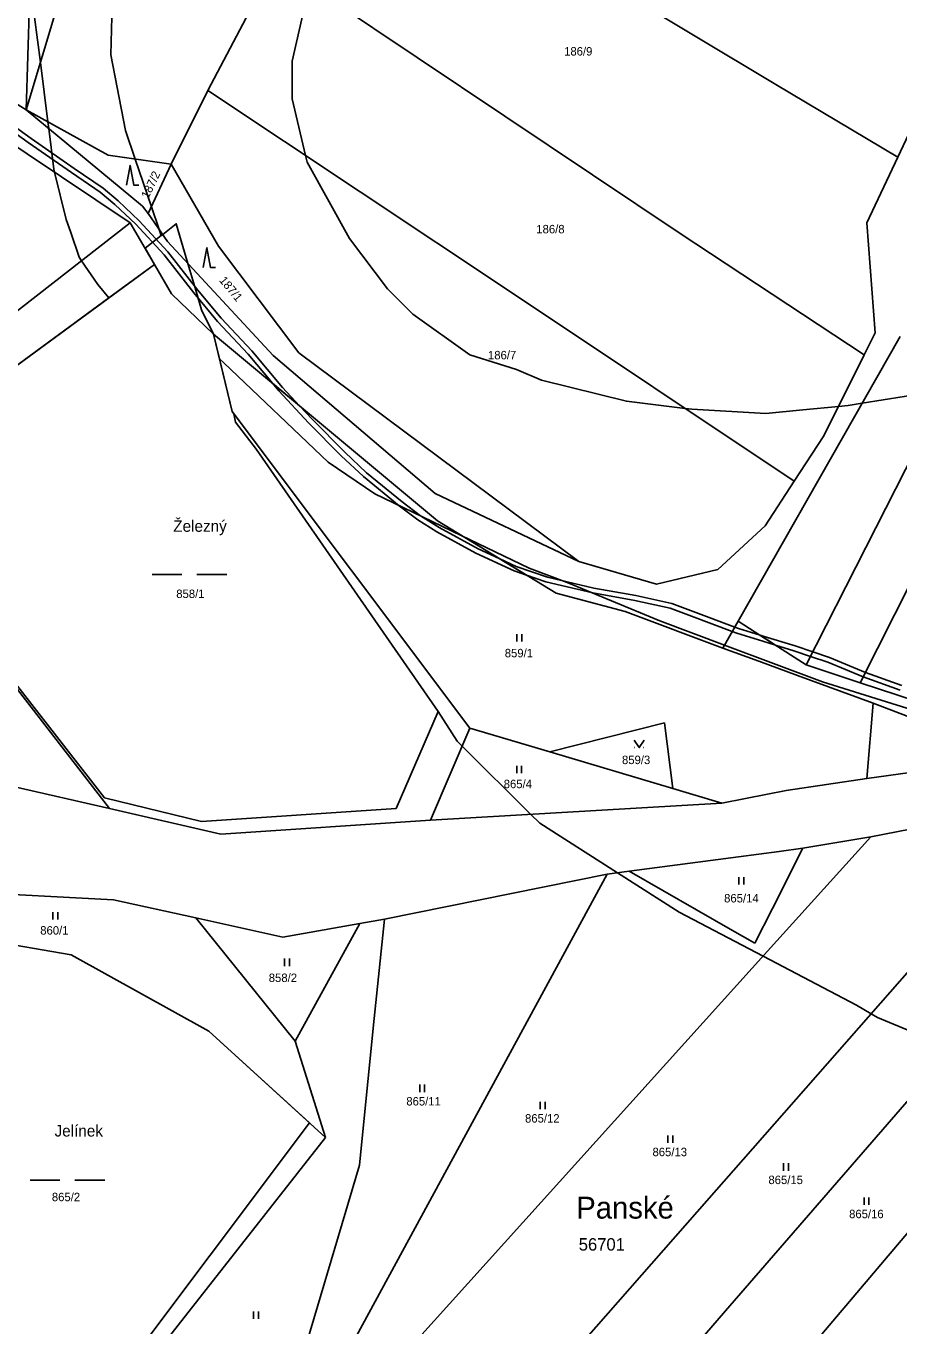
# Model space of a CAD drawing. Extents: x -749173 to -746119, y -1132678 to -1130338.
# Drawn here: x -747283.8 to -747108.1, y -1131870.4 to -1131608.6 of the extents above; entities that cross this region are included whole.
import ezdxf

# ---------------------------------------------------------------- set-up
doc = ezdxf.new("R2010")
doc.units = 0
for name, color, linetype in [('Vrstva 1', 7, 'Continuous'), ('Vrstva 15', 7, 'Continuous'), ('Vrstva 18', 7, 'Continuous'), ('Vrstva 25', 7, 'Continuous'), ('Vrstva 30', 7, 'Continuous'), ('Vrstva 52', 7, 'Continuous'), ('Vrstva 53', 7, 'Continuous'), ('Vrstva 6', 7, 'Continuous')]:
    doc.layers.add(name, color=color, linetype=linetype)

msp = doc.modelspace()

# ---------------------------------------------------------------- linework, layer by layer
at = {"layer": 'Vrstva 1'}
for points in [[(-747283.76, -1131625.43), (-747282.45, -1131581.86)], [(-747273.69, -1131591.9), (-747283.76, -1131625.43)], [(-747108.32, -1131634.98), (-747091.75, -1131599.73)], [(-747305.55, -1131611.85), (-747283.76, -1131625.43)], [(-747283.76, -1131625.43), (-747267.27, -1131634.55)], [(-747283.76, -1131625.43), (-747260.33, -1131644.82)], [(-747290.52, -1131629.64), (-747262.86, -1131648.18)], [(-747267.27, -1131634.55), (-747254.6, -1131636.41)], [(-747254.6, -1131636.41), (-747245.07, -1131652.89)], [(-747114.54, -1131648.21), (-747108.32, -1131634.98)], [(-747260.33, -1131644.82), (-747259.18, -1131646.33)], [(-747259.18, -1131646.33), (-747255.29, -1131651.97)], [(-747322.41, -1131694.68), (-747262.86, -1131648.18)], [(-747262.86, -1131648.18), (-747257.91, -1131656.57)], [(-747112.86, -1131670.34), (-747114.54, -1131648.21)], [(-747255.29, -1131651.97), (-747234.06, -1131674.93)], [(-747245.07, -1131652.89), (-747228.87, -1131674.36)], [(-747317.79, -1131700.5), (-747257.91, -1131656.57)], [(-747257.91, -1131656.57), (-747254.48, -1131662.48)], [(-747254.48, -1131662.48), (-747246.06, -1131670.63)], [(-747200.93, -1131708.24), (-747246.06, -1131670.63)], [(-747246.06, -1131670.63), (-747242.32, -1131686.21)], [(-747107.8, -1131671.12), (-747140.43, -1131728.4)], [(-747115.08, -1131674.81), (-747112.86, -1131670.34)], [(-747234.06, -1131674.93), (-747201.42, -1131702.74)], [(-747228.87, -1131674.36), (-747172.52, -1131716.41)], [(-747123.18, -1131691.12), (-747115.08, -1131674.81)], [(-747242.32, -1131686.21), (-747194.42, -1131749.94)], [(-747129.15, -1131700.25), (-747123.18, -1131691.12)], [(-747267.01, -1131766.16), (-747317.79, -1131700.5)], [(-747135, -1131709.19), (-747129.15, -1131700.25)], [(-747201.42, -1131702.74), (-747172.52, -1131716.41)], [(-747177.09, -1131722.8), (-747200.93, -1131708.24)], [(-747144.51, -1131718.02), (-747135, -1131709.19)], [(-747172.52, -1131716.41), (-747156.9, -1131720.96)], [(-747156.9, -1131720.96), (-747144.51, -1131718.02)], [(-747163.2, -1131726.49), (-747177.09, -1131722.8)], [(-747143.51, -1131733.86), (-747163.2, -1131726.49)], [(-747140.43, -1131728.4), (-747143.51, -1131733.86)], [(-747135.85, -1131731.36), (-747140.43, -1131728.4)], [(-747128.24, -1131736.28), (-747135.85, -1131731.36)], [(-747136.3, -1131736.51), (-747143.51, -1131733.86)], [(-747128.51, -1131739.37), (-747136.3, -1131736.51)], [(-747126.73, -1131737.25), (-747128.24, -1131736.28)], [(-747115.85, -1131740.82), (-747126.73, -1131737.25)], [(-747113.28, -1131744.96), (-747128.51, -1131739.37)], [(-747104.57, -1131744.53), (-747115.85, -1131740.82)], [(-747113.28, -1131744.96), (-747114.55, -1131760.12)], [(-747084.49, -1131755.95), (-747113.28, -1131744.96)], [(-747178.35, -1131754.73), (-747155.26, -1131748.88)], [(-747153.61, -1131762.1), (-747155.26, -1131748.88)], [(-747194.42, -1131749.94), (-747202.38, -1131768.48)], [(-747194.42, -1131749.94), (-747178.35, -1131754.73)], [(-747178.35, -1131754.73), (-747153.61, -1131762.1)], [(-747114.55, -1131760.12), (-747084.49, -1131755.95)], [(-747130.74, -1131762.5), (-747114.55, -1131760.12)], [(-747267.01, -1131766.16), (-747286.37, -1131761.74)], [(-747153.61, -1131762.1), (-747143.72, -1131765.05)], [(-747138.98, -1131764.12), (-747130.74, -1131762.5)], [(-747143.72, -1131765.05), (-747202.38, -1131768.48)], [(-747143.72, -1131765.05), (-747138.98, -1131764.12)], [(-747075.87, -1131764.45), (-747113.75, -1131771.83)], [(-747244.55, -1131771.35), (-747267.01, -1131766.16)], [(-747202.38, -1131768.48), (-747244.55, -1131771.35)], [(-747113.75, -1131771.83), (-747127.4, -1131774.15)], [(-747140.35, -1131775.86), (-747162.4, -1131778.78)], [(-747132.18, -1131774.78), (-747140.35, -1131775.86)], [(-747127.4, -1131774.15), (-747132.18, -1131774.78)], [(-747166.79, -1131779.35), (-747211.65, -1131788.43)], [(-747162.4, -1131778.78), (-747166.79, -1131779.35)], [(-747296.48, -1131782.93), (-747266.19, -1131784.57)], [(-747266.19, -1131784.57), (-747249.62, -1131788.14)], [(-747249.62, -1131788.14), (-747232.12, -1131792.08)], [(-747229.61, -1131813), (-747249.62, -1131788.14)], [(-747211.65, -1131788.43), (-747216.62, -1131789.31)], [(-747213.89, -1131810.39), (-747211.65, -1131788.43)], [(-747274.72, -1131795.65), (-747308.97, -1131789.7)], [(-747232.12, -1131792.08), (-747216.62, -1131789.31)], [(-747216.62, -1131789.31), (-747229.61, -1131813)], [(-747246.96, -1131810.99), (-747274.72, -1131795.65)], [(-747223.51, -1131832.44), (-747246.96, -1131810.99)], [(-747216.68, -1131837.99), (-747213.89, -1131810.39)], [(-747229.61, -1131813), (-747223.51, -1131832.44)], [(-747265.2, -1131885.54), (-747223.51, -1131832.44)], [(-747230.08, -1131883.19), (-747216.68, -1131837.99)]]:
    msp.add_lwpolyline(points, dxfattribs=at)
at = {"layer": 'Vrstva 25'}
for p, q in [((-747258.4, -1131719.04), (-747252.4, -1131719.04)), ((-747249.4, -1131719.04), (-747243.4, -1131719.04)), ((-747185, -1131731.02), (-747185, -1131732.52)), ((-747184, -1131732.52), (-747184, -1131731.02)), ((-747161.31, -1131753.88), (-747161.21, -1131753.88)), ((-747159.51, -1131753.88), (-747159.41, -1131753.88)), ((-747185.02, -1131757.53), (-747185.02, -1131759.03)), ((-747184.02, -1131759.03), (-747184.02, -1131757.53)), ((-747140.27, -1131779.99), (-747140.27, -1131781.49)), ((-747139.27, -1131781.49), (-747139.27, -1131779.99)), ((-747278.37, -1131787.02), (-747278.37, -1131788.52)), ((-747277.37, -1131788.52), (-747277.37, -1131787.02)), ((-747231.74, -1131796.39), (-747231.74, -1131797.89)), ((-747230.74, -1131797.89), (-747230.74, -1131796.39)), ((-747204.55, -1131821.77), (-747204.55, -1131823.27)), ((-747203.55, -1131823.27), (-747203.55, -1131821.77)), ((-747180.28, -1131825.21), (-747180.28, -1131826.71)), ((-747179.28, -1131826.71), (-747179.28, -1131825.21)), ((-747154.61, -1131831.98), (-747154.61, -1131833.48)), ((-747153.61, -1131833.48), (-747153.61, -1131831.98)), ((-747131.31, -1131837.6), (-747131.31, -1131839.1)), ((-747130.31, -1131839.1), (-747130.31, -1131837.6)), ((-747282.96, -1131841), (-747276.96, -1131841)), ((-747273.96, -1131841), (-747267.96, -1131841)), ((-747115.1, -1131844.47), (-747115.1, -1131845.97)), ((-747114.1, -1131845.97), (-747114.1, -1131844.47)), ((-747238, -1131867.43), (-747238, -1131868.93)), ((-747237, -1131868.93), (-747237, -1131867.43))]:
    msp.add_line(p, q, dxfattribs=at)
for points in [[(-747263.59, -1131640.62), (-747262.84, -1131636.62), (-747262.09, -1131640.62), (-747261.09, -1131640.62)], [(-747248.13, -1131657.21), (-747247.38, -1131653.21), (-747246.63, -1131657.21), (-747245.63, -1131657.21)], [(-747161.36, -1131752.38), (-747160.36, -1131753.88), (-747159.36, -1131752.38)]]:
    msp.add_lwpolyline(points, dxfattribs=at)
at = {"layer": 'Vrstva 30'}
for points in [[(-747283.36, -1131632.04), (-747292.6, -1131625.39)], [(-747292.02, -1131624.57), (-747282.78, -1131631.22)], [(-747282.78, -1131631.22), (-747274.1, -1131637.24)], [(-747274.66, -1131638.06), (-747283.36, -1131632.04)], [(-747268.88, -1131641.99), (-747274.66, -1131638.06)], [(-747274.1, -1131637.24), (-747268.28, -1131641.19)], [(-747265.94, -1131644.47), (-747268.88, -1131641.99)], [(-747268.28, -1131641.19), (-747265.26, -1131643.73)], [(-747261.71, -1131648.47), (-747265.94, -1131644.47)], [(-747265.26, -1131643.73), (-747261, -1131647.77)], [(-747255.99, -1131654.66), (-747261.71, -1131648.47)], [(-747261, -1131647.77), (-747255.23, -1131654.02)], [(-747250.04, -1131662.3), (-747255.99, -1131654.66)], [(-747255.23, -1131654.02), (-747249.26, -1131661.66)], [(-747245.22, -1131668.05), (-747250.04, -1131662.3)], [(-747249.26, -1131661.66), (-747244.48, -1131667.39)], [(-747239.07, -1131674.66), (-747245.22, -1131668.05)], [(-747244.48, -1131667.39), (-747238.33, -1131674)], [(-747234.19, -1131680.52), (-747239.07, -1131674.66)], [(-747238.33, -1131674), (-747232.17, -1131681.39)], [(-747232.91, -1131682.05), (-747234.19, -1131680.52)], [(-747234.19, -1131680.52), (-747228.73, -1131685.07)], [(-747228.73, -1131685.07), (-747234.19, -1131680.52)], [(-747232.17, -1131681.39), (-747228.73, -1131685.07)], [(-747226.94, -1131688.46), (-747232.91, -1131682.05)], [(-747228.73, -1131685.07), (-747226.22, -1131687.76)], [(-747220.32, -1131695.09), (-747226.94, -1131688.46)], [(-747226.22, -1131687.76), (-747219.62, -1131694.37)], [(-747219.62, -1131694.37), (-747215.23, -1131698.52)], [(-747215.89, -1131699.28), (-747220.32, -1131695.09)], [(-747208.69, -1131705.2), (-747215.89, -1131699.28)], [(-747215.23, -1131698.52), (-747208.07, -1131704.42)], [(-747204.94, -1131708.02), (-747208.69, -1131705.2)], [(-747208.07, -1131704.42), (-747204.37, -1131707.2)], [(-747204.37, -1131707.2), (-747200.6, -1131709.57)], [(-747201.12, -1131710.43), (-747204.94, -1131708.02)], [(-747193.24, -1131714.74), (-747201.12, -1131710.43)], [(-747200.6, -1131709.57), (-747192.78, -1131713.84)], [(-747185.52, -1131718.31), (-747193.24, -1131714.74)], [(-747192.78, -1131713.84), (-747188.52, -1131715.82)], [(-747188.52, -1131715.82), (-747185.14, -1131717.39)], [(-747188.52, -1131715.82), (-747183.02, -1131719.18)], [(-747183.02, -1131719.18), (-747188.52, -1131715.82)], [(-747185.14, -1131717.39), (-747178.84, -1131719.57)], [(-747183.02, -1131719.18), (-747185.52, -1131718.31)], [(-747179.12, -1131720.53), (-747183.02, -1131719.18)], [(-747169.7, -1131722.73), (-747179.12, -1131720.53)], [(-747178.84, -1131719.57), (-747169.5, -1131721.75)], [(-747161.21, -1131724.25), (-747169.7, -1131722.73)], [(-747169.5, -1131721.75), (-747161.02, -1131723.27)], [(-747161.02, -1131723.27), (-747153.81, -1131724.86)], [(-747154.09, -1131725.82), (-747161.21, -1131724.25)], [(-747149.86, -1131727.41), (-747154.09, -1131725.82)], [(-747153.81, -1131724.86), (-747149.5, -1131726.47)], [(-747141.62, -1131730.51), (-747149.86, -1131727.41)], [(-747149.5, -1131726.47), (-747141.12, -1131729.63)], [(-747140.69, -1131730.86), (-747141.62, -1131730.51)], [(-747141.12, -1131729.63), (-747140.35, -1131729.92)], [(-747135.5, -1131732.46), (-747140.69, -1131730.86)], [(-747140.35, -1131729.92), (-747136.02, -1131731.25)], [(-747136.02, -1131731.25), (-747135.2, -1131731.5)], [(-747132.95, -1131733.24), (-747136.02, -1131731.25)], [(-747136.02, -1131731.25), (-747132.95, -1131733.24)], [(-747132.95, -1131733.24), (-747135.5, -1131732.46)], [(-747135.2, -1131731.5), (-747128.94, -1131733.41)], [(-747129.24, -1131734.37), (-747132.95, -1131733.24)], [(-747128.94, -1131733.41), (-747125.4, -1131734.62)], [(-747125.85, -1131735.53), (-747129.24, -1131734.37)], [(-747125.85, -1131735.53), (-747125.4, -1131734.62)], [(-747125.4, -1131734.62), (-747125.85, -1131735.53)], [(-747122.39, -1131736.71), (-747125.85, -1131735.53)], [(-747125.4, -1131734.62), (-747122.04, -1131735.77)], [(-747122.04, -1131735.77), (-747114.8, -1131738.74)], [(-747115.26, -1131739.64), (-747122.39, -1131736.71)], [(-747114.8, -1131738.74), (-747115.26, -1131739.64)], [(-747115.26, -1131739.64), (-747114.8, -1131738.74)], [(-747114.8, -1131738.74), (-747107.48, -1131741.38)], [(-747107.8, -1131742.32), (-747115.26, -1131739.64)]]:
    msp.add_lwpolyline(points, dxfattribs=at)
at = {"layer": 'Vrstva 52'}
for points in [[(-747256.56, -1131650.75), (-747256.98, -1131649.52), (-747258.54, -1131644.94), (-747261.8, -1131635.35), (-747263.75, -1131629.62), (-747266.75, -1131614.37), (-747266.31, -1131599)], [(-747227.19, -1131636), (-747227.51, -1131634.64), (-747230.19, -1131623.25), (-747230.19, -1131615.62), (-747227.94, -1131605.66)], [(-747267.13, -1131663.33), (-747269.31, -1131660.62), (-747272.64, -1131655.82), (-747273.12, -1131655.12), (-747274.8, -1131650.13), (-747275.69, -1131647.5), (-747278.03, -1131638.01), (-747278.19, -1131637.37), (-747279.22, -1131629.18), (-747279.39, -1131627.84), (-747280.9, -1131615.91), (-747282.06, -1131606.75)], [(-747098.58, -1131681.8), (-747115.44, -1131684.53), (-747118.31, -1131685), (-747120.23, -1131685.19), (-747127.43, -1131685.89), (-747134.87, -1131686.62), (-747149.75, -1131685.75), (-747151.1, -1131685.58), (-747162.94, -1131684.12), (-747180, -1131679.87), (-747185.06, -1131677.75), (-747194.44, -1131674.75), (-747205.94, -1131666.62), (-747211, -1131661.5), (-747218.69, -1131651.37), (-747227.19, -1131636)], [(-747256.56, -1131650.75), (-747256.28, -1131650.53), (-747253.56, -1131648.37), (-747251.19, -1131656.4), (-747249.62, -1131661.75), (-747248.44, -1131665.75), (-747246.04, -1131670.64), (-747244.87, -1131675.57)], [(-747267.13, -1131663.33), (-747257.91, -1131656.57), (-747259.84, -1131653.29), (-747256.56, -1131650.75)], [(-747209.31, -1131766.12), (-747248.44, -1131768.75), (-747268, -1131764), (-747317.58, -1131700.34), (-747267.13, -1131663.33)], [(-747244.87, -1131675.57), (-747242.32, -1131686.21), (-747241.96, -1131686.69), (-747241.62, -1131688.37), (-747237.37, -1131693.87), (-747200.81, -1131746.62)], [(-747054.06, -1131755.5), (-747069, -1131753.87), (-747069.29, -1131753.82), (-747081.75, -1131751.75), (-747082.99, -1131751.57), (-747093.62, -1131750), (-747123.44, -1131740.62), (-747143.16, -1131733.24), (-747156.19, -1131728.37), (-747174.87, -1131720.62), (-747182.5, -1131717.75), (-747196.17, -1131711.15), (-747213.56, -1131702.75), (-747222.94, -1131696.37), (-747244, -1131676.37), (-747244.87, -1131675.57)], [(-747200.81, -1131746.62), (-747209.31, -1131766.12)], [(-747097.22, -1131814.55), (-747112.37, -1131808.25), (-747113.66, -1131807.49), (-747116.62, -1131805.75), (-747135.41, -1131795.87), (-747152.31, -1131787), (-747164.74, -1131779.08), (-747180.37, -1131769.12), (-747182.21, -1131767.3), (-747196, -1131753.62), (-747197, -1131752.62), (-747200.81, -1131746.62)], [(-747347.62, -1131837.7), (-747343.68, -1131839.79), (-747342.44, -1131842.28), (-747333.94, -1131859.37), (-747333.42, -1131859.37), (-747332.1, -1131862.53), (-747307.27, -1131850), (-747308.51, -1131806.18), (-747308.97, -1131789.7), (-747274.72, -1131795.65), (-747246.96, -1131810.99), (-747226.76, -1131829.48), (-747266.75, -1131882.75), (-747263.66, -1131883.58), (-747265.2, -1131885.54), (-747226.07, -1131896.73), (-747204.18, -1131909.18), (-747161.04, -1131934.49), (-747154.1, -1131938.56), (-747140.46, -1131946.56), (-747107.18, -1131952.81), (-747078.4, -1131964.27), (-747078.75, -1131965.25)]]:
    msp.add_lwpolyline(points, dxfattribs=at)
at = {"layer": 'Vrstva 6'}
for points in [[(-747182.23, -1131590.68), (-747132.82, -1131620.3)], [(-747233.69, -1131595.9), (-747247.17, -1131621.56)], [(-747222.7, -1131603.02), (-747152.14, -1131650.37)], [(-747132.82, -1131620.3), (-747108.32, -1131634.98)], [(-747247.17, -1131621.56), (-747254.6, -1131636.41)], [(-747247.17, -1131621.56), (-747185.86, -1131662.35)], [(-747254.6, -1131636.41), (-747259.18, -1131646.33)], [(-747152.14, -1131650.37), (-747115.08, -1131674.81)], [(-747185.86, -1131662.35), (-747129.15, -1131700.25)], [(-747102.71, -1131689.93), (-747126.73, -1131737.25)], [(-747101.98, -1131713.33), (-747115.85, -1131740.82)], [(-747075.87, -1131764.45), (-747139.41, -1131836.82)], [(-747055.5, -1131766.4), (-747142.97, -1131867.35)], [(-747113.75, -1131771.83), (-747134.52, -1131794.88)], [(-747133.52, -1131786.29), (-747127.4, -1131774.15)], [(-747166.79, -1131779.35), (-747224.99, -1131886.58)], [(-747162.4, -1131778.78), (-747142.05, -1131790.43)], [(-747137.05, -1131793.3), (-747133.52, -1131786.29)], [(-747142.05, -1131790.43), (-747137.05, -1131793.3)], [(-747134.52, -1131794.88), (-747143.77, -1131805.15)], [(-747143.77, -1131805.15), (-747220.07, -1131889.85)], [(-747139.41, -1131836.82), (-747148.7, -1131847.4)], [(-747148.7, -1131847.4), (-747198.55, -1131904.18)], [(-747135.89, -1131886.55), (-747102.76, -1131847.44)], [(-747142.97, -1131867.35), (-747152.3, -1131878.12)]]:
    msp.add_lwpolyline(points, dxfattribs=at)

# ---------------------------------------------------------------- texts
at = {"layer": 'Vrstva 15'}
for s, height, p in [('Železný', 2.3, (-747254.15, -1131710.42)), ('Jelínek', 2.3, (-747278.05, -1131832.22)), ('Panské', 4.4, (-747173.02, -1131848.75))]:
    msp.add_text(s, height=height, dxfattribs=at).set_placement(p)
at = {"layer": 'Vrstva 18'}
for s, p in [('186/9', (-747175.47, -1131614.5)), ('186/8', (-747181.07, -1131650.31)), ('186/7', (-747190.8, -1131675.69)), ('858/1', (-747253.55, -1131723.76)), ('859/1', (-747187.42, -1131735.7)), ('859/3', (-747163.82, -1131757.21)), ('865/4', (-747187.63, -1131762.06)), ('865/14', (-747143.26, -1131785.07)), ('860/1', (-747280.93, -1131791.55)), ('858/2', (-747234.93, -1131801.1)), ('865/11', (-747207.24, -1131825.97)), ('865/12', (-747183.34, -1131829.41)), ('865/13', (-747157.68, -1131836.18)), ('865/15', (-747134.34, -1131841.8)), ('865/2', (-747278.59, -1131845.25)), ('865/16', (-747118.1, -1131848.67))]:
    msp.add_text(s, height=1.7, dxfattribs=at).set_placement(p)
for s, rotation, p in [('187/2', 64.2852, (-747259.17, -1131643.44)), ('187/1', 309.737, (-747245.01, -1131659.83))]:
    msp.add_text(s, height=1.7, rotation=rotation, dxfattribs=at).set_placement(p)
at = {"layer": 'Vrstva 53'}
msp.add_text('56701', height=2.5, dxfattribs=at).set_placement((-747172.53, -1131855.19))

doc.saveas('drawing.dxf')
